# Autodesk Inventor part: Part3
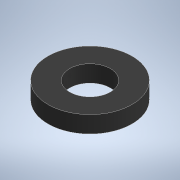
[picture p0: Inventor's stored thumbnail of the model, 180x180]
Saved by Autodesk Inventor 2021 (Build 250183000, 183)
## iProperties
Created: 2023-08
Part Number: Part3
Material: Rubber
Document SubType Name: Modeling
Designer: canad
Density: 0.93 g/cm^3
Appearance: Rubber - Black
Author: canad
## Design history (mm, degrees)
sketch "Sketch1"
  geometry: C1 r 125 at (0, 0); C2 r 60.5 at (0, 0); 1 further point
  constraints: 2 centre point, 2 coincident
  dimensions: "d0" = 250 diameter of C1; "d21" = 121 diameter of C2
workplane "Work Plane1"
extrude "Extrusion2" new body sketch "Sketch1" distance "d24" = 50; taper "d25" = 0 deg
body "Solid3"
